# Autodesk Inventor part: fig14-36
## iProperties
Created: 2005-03
Part Number: fig14-36
Document SubType Name: Sheet Metal
Designer: CADCIM
Manufacturer: Standard
Standards Organization: Custom
Author: CADCIM
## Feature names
1. Plate1
2. Plate2
3. Bend1
4. Plate3
5. Bend2
